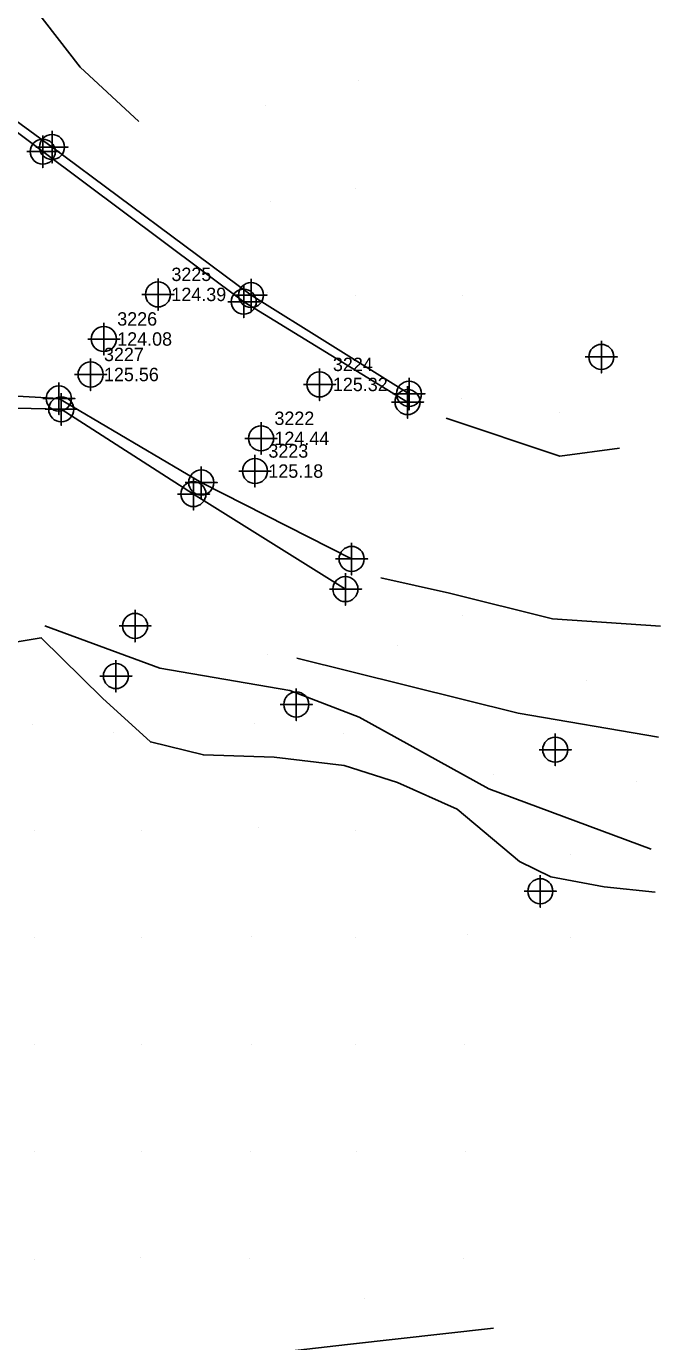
# Model space of a CAD drawing. Extents: x 2312183 to 2312663, y 819676 to 820746.
# Drawn here: x 2312544.8 to 2312663.2, y 819940.8 to 820186.5 of the extents above; entities that cross this region are included whole.
import ezdxf

# ---------------------------------------------------------------- set-up
doc = ezdxf.new("R2010")
doc.units = 0
for name, color, linetype in [('Exist DTM Breakline', 7, 'Continuous'), ('Exist DTM Breakline Cogo Point CELL', 7, 'Continuous'), ('Exist DTM Regular Point CELL', 7, 'Continuous'), ('Exist DTM Regular Point Underwater CELL', 7, 'Continuous'), ('Exist DTM Regular Point Underwater Cogo Elevation', 7, 'Continuous'), ('Exist DTM Regular Point Underwater Cogo Number', 7, 'Continuous'), ('Exist Hydro Stream or Body of Water', 7, 'Continuous'), ('Exist Hydro Stream or Body of Water Cogo Point CELL', 7, 'Continuous'), ('PH Exist DTM Breakline', 7, 'Continuous'), ('PH Exist DTM Point', 7, 'Continuous')]:
    doc.layers.add(name, color=color, linetype=linetype)

msp = doc.modelspace()

# ---------------------------------------------------------------- linework, layer by layer
at = {"layer": 'Exist DTM Breakline'}
for p, q in [((2312586.75, 820136.34), (2312616.24, 820117.89)), ((2312576, 820099.16), (2312604.37, 820081.4))]:
    msp.add_line(p, q, dxfattribs=at)
for points in [[(2312522.1, 820208.19), (2312528.71, 820183.41), (2312536.41, 820173.61), (2312549.61, 820163.99)], [(2312549.61, 820163.99), (2312586.75, 820136.34)], [(2312469.05, 820107.68), (2312503.56, 820116.05), (2312551.33, 820115), (2312576, 820099.16)]]:
    msp.add_lwpolyline(points, dxfattribs=at)
at = {"layer": 'Exist DTM Breakline Cogo Point CELL'}
for points in [[(2312549.61, 820166.99), (2312549.61, 820160.99), (2312549.61, 820163.99), (2312552.61, 820163.99), (2312546.61, 820163.99)], [(2312586.75, 820139.34), (2312586.75, 820133.34), (2312586.75, 820136.34), (2312589.75, 820136.34), (2312583.75, 820136.34)], [(2312616.24, 820120.89), (2312616.24, 820114.89), (2312616.24, 820117.89), (2312619.24, 820117.89), (2312613.24, 820117.89)], [(2312551.33, 820118), (2312551.33, 820112), (2312551.33, 820115), (2312554.33, 820115), (2312548.33, 820115)], [(2312576, 820102.16), (2312576, 820096.16), (2312576, 820099.16), (2312579, 820099.16), (2312573, 820099.16)], [(2312604.37, 820084.4), (2312604.37, 820078.4), (2312604.37, 820081.4), (2312607.37, 820081.4), (2312601.37, 820081.4)]]:
    msp.add_lwpolyline(points, dxfattribs=at)
for centre in [(2312549.61, 820163.99), (2312586.75, 820136.34), (2312616.24, 820117.89), (2312551.33, 820115), (2312576, 820099.16), (2312604.37, 820081.4)]:
    msp.add_circle(centre, 2.34, dxfattribs=at)
at = {"layer": 'Exist DTM Regular Point CELL'}
for points in [[(2312652.13, 820127.78), (2312652.13, 820121.78), (2312652.13, 820124.78), (2312655.13, 820124.78), (2312649.13, 820124.78)], [(2312565.11, 820077.53), (2312565.11, 820071.53), (2312565.11, 820074.53), (2312568.11, 820074.53), (2312562.11, 820074.53)], [(2312561.53, 820068.16), (2312561.53, 820062.16), (2312561.53, 820065.16), (2312564.53, 820065.16), (2312558.53, 820065.16)], [(2312595.2, 820062.85), (2312595.2, 820056.85), (2312595.2, 820059.85), (2312598.2, 820059.85), (2312592.2, 820059.85)], [(2312643.53, 820054.41), (2312643.53, 820048.41), (2312643.53, 820051.41), (2312646.53, 820051.41), (2312640.53, 820051.41)], [(2312640.74, 820027.96), (2312640.74, 820021.96), (2312640.74, 820024.96), (2312643.74, 820024.96), (2312637.74, 820024.96)]]:
    msp.add_lwpolyline(points, dxfattribs=at)
for centre in [(2312652.13, 820124.78), (2312565.11, 820074.53), (2312561.53, 820065.16), (2312595.2, 820059.85), (2312643.53, 820051.41), (2312640.74, 820024.96)]:
    msp.add_circle(centre, 2.34, dxfattribs=at)
at = {"layer": 'Exist DTM Regular Point Underwater CELL'}
for points in [[(2312569.39, 820139.46), (2312569.39, 820133.46), (2312569.39, 820136.46), (2312572.39, 820136.46), (2312566.39, 820136.46)], [(2312559.28, 820131.13), (2312559.28, 820125.13), (2312559.28, 820128.13), (2312562.28, 820128.13), (2312556.28, 820128.13)], [(2312556.81, 820124.5), (2312556.81, 820118.5), (2312556.81, 820121.5), (2312559.81, 820121.5), (2312553.81, 820121.5)], [(2312599.53, 820122.64), (2312599.53, 820116.64), (2312599.53, 820119.64), (2312602.53, 820119.64), (2312596.53, 820119.64)], [(2312588.62, 820112.57), (2312588.62, 820106.57), (2312588.62, 820109.57), (2312591.62, 820109.57), (2312585.62, 820109.57)], [(2312587.49, 820106.46), (2312587.49, 820100.46), (2312587.49, 820103.46), (2312590.49, 820103.46), (2312584.49, 820103.46)]]:
    msp.add_lwpolyline(points, dxfattribs=at)
for centre in [(2312569.39, 820136.46), (2312559.28, 820128.13), (2312556.81, 820121.5), (2312599.53, 820119.64), (2312588.62, 820109.57), (2312587.49, 820103.46)]:
    msp.add_circle(centre, 2.34, dxfattribs=at)
at = {"layer": 'Exist Hydro Stream or Body of Water'}
for p, q in [((2312585.39, 820135.1), (2312615.96, 820116.34)), ((2312577.46, 820101.32), (2312605.52, 820087.05))]:
    msp.add_line(p, q, dxfattribs=at)
for points in [[(2312524.84, 820178.65), (2312535.66, 820172.32), (2312547.88, 820163.13)], [(2312547.88, 820163.13), (2312585.39, 820135.1)], [(2312393.18, 820036.93), (2312414.57, 820059.59), (2312427.23, 820072.7), (2312438.05, 820092.67), (2312468.54, 820109.59), (2312503.07, 820119.67), (2312550.88, 820117.01)], [(2312550.88, 820117.01), (2312577.46, 820101.32)]]:
    msp.add_lwpolyline(points, dxfattribs=at)
at = {"layer": 'Exist Hydro Stream or Body of Water Cogo Point CELL'}
for points in [[(2312544.88, 820163.13), (2312550.88, 820163.13), (2312547.88, 820163.13), (2312547.88, 820160.13), (2312547.88, 820166.13)], [(2312582.39, 820135.1), (2312588.39, 820135.1), (2312585.39, 820135.1), (2312585.39, 820132.1), (2312585.39, 820138.1)], [(2312547.88, 820117.01), (2312553.88, 820117.01), (2312550.88, 820117.01), (2312550.88, 820114.01), (2312550.88, 820120.01)], [(2312612.96, 820116.34), (2312618.96, 820116.34), (2312615.96, 820116.34), (2312615.96, 820113.34), (2312615.96, 820119.34)], [(2312574.46, 820101.32), (2312580.46, 820101.32), (2312577.46, 820101.32), (2312577.46, 820098.32), (2312577.46, 820104.32)], [(2312602.52, 820087.05), (2312608.52, 820087.05), (2312605.52, 820087.05), (2312605.52, 820084.05), (2312605.52, 820090.05)]]:
    msp.add_lwpolyline(points, dxfattribs=at)
for centre in [(2312547.88, 820163.13), (2312585.39, 820135.1), (2312550.88, 820117.01), (2312615.96, 820116.34), (2312577.46, 820101.32), (2312605.52, 820087.05)]:
    msp.add_circle(centre, 2.34, dxfattribs=at)
at = {"layer": 'PH Exist DTM Breakline'}
for points in [[(2312531.48, 820219.81), (2312535.01, 820208.04), (2312541.96, 820195.62), (2312554.87, 820178.93), (2312565.84, 820168.78)], [(2312509.03, 820114.01), (2312517.15, 820110.06), (2312518.21, 820106.25), (2312517.15, 820100.47), (2312517.95, 820089.08), (2312520.08, 820081.64), (2312522.64, 820074.56), (2312526.51, 820071.39), (2312534, 820070.09), (2312547.61, 820072.32), (2312559.01, 820061.03), (2312567.96, 820052.87), (2312577.86, 820050.42), (2312591.06, 820050.01), (2312604.11, 820048.43), (2312614.06, 820045.26), (2312625.22, 820040.28), (2312636.84, 820030.53), (2312642.68, 820027.68), (2312652.67, 820025.8), (2312662.18, 820024.81)], [(2312623.16, 820113.36), (2312644.38, 820106.22), (2312655.5, 820107.75)], [(2312663.2, 820074.47), (2312643.01, 820075.86), (2312623.82, 820080.64), (2312610.97, 820083.52)], [(2312661.41, 820032.82), (2312631.11, 820044.08), (2312606.93, 820057.49), (2312594.01, 820062.47), (2312569.74, 820066.65), (2312548.24, 820074.57)], [(2312595.27, 820068.49), (2312636.63, 820058.21), (2312662.81, 820053.73)], [(2312513.82, 819939.75), (2312519.38, 819936.51), (2312526.86, 819933.99), (2312535.44, 819932.71), (2312543.63, 819933), (2312575.99, 819937.01), (2312604.73, 819940.27), (2312632.01, 819943.32)]]:
    msp.add_lwpolyline(points, dxfattribs=at)
at = {"layer": 'PH Exist DTM Point'}
for p, q in [((2312606.76, 820176.39), (2312606.76, 820176.39)), ((2312589.47, 820171.83), (2312589.47, 820171.83)), ((2312606.33, 820156.23), (2312606.33, 820156.23)), ((2312590.32, 820153.74), (2312590.32, 820153.74)), ((2312589.9, 820136.75), (2312589.9, 820136.75)), ((2312606.33, 820136.21), (2312606.33, 820136.21)), ((2312626.29, 820136.34), (2312626.29, 820136.34)), ((2312606.22, 820123.69), (2312606.22, 820123.69)), ((2312626.11, 820117.02), (2312626.11, 820117.02)), ((2312644.37, 820114.43), (2312644.37, 820114.43)), ((2312626.24, 820076.54), (2312626.24, 820076.54)), ((2312589.88, 820069.21), (2312589.88, 820069.21)), ((2312614.06, 820070.83), (2312614.06, 820070.83)), ((2312649.27, 820064.24), (2312649.27, 820064.24)), ((2312587.44, 820056.29), (2312587.44, 820056.29)), ((2312545.94, 820056.11), (2312545.94, 820056.11)), ((2312561.05, 820054.53), (2312561.05, 820054.53)), ((2312604, 820054.51), (2312604, 820054.51)), ((2312631.94, 820046.75), (2312631.94, 820046.75)), ((2312658.73, 820045.44), (2312658.73, 820045.44)), ((2312588.09, 820036.82), (2312588.09, 820036.82)), ((2312546.32, 820036.25), (2312546.32, 820036.25)), ((2312566.32, 820036.25), (2312566.32, 820036.25)), ((2312606.33, 820036.25), (2312606.33, 820036.25)), ((2312646.35, 820031.86), (2312646.35, 820031.86)), ((2312546.32, 820016.25), (2312546.32, 820016.25)), ((2312566.32, 820016.25), (2312566.32, 820016.25)), ((2312586.86, 820016.42), (2312586.86, 820016.42)), ((2312606.32, 820016.25), (2312606.32, 820016.25)), ((2312627.13, 820016.84), (2312627.13, 820016.84)), ((2312646.32, 820016.25), (2312646.32, 820016.25)), ((2312546.32, 819996.25), (2312546.32, 819996.25)), ((2312566.32, 819996.25), (2312566.32, 819996.25)), ((2312586.75, 819996.38), (2312586.75, 819996.38)), ((2312606.32, 819996.25), (2312606.32, 819996.25)), ((2312626.62, 819996.34), (2312626.62, 819996.34)), ((2312546.32, 819976.25), (2312546.32, 819976.25)), ((2312566.32, 819976.25), (2312566.32, 819976.25)), ((2312586.57, 819976.32), (2312586.57, 819976.32)), ((2312606.35, 819976.25), (2312606.35, 819976.25)), ((2312626.8, 819976.4), (2312626.8, 819976.4)), ((2312546.32, 819956.25), (2312546.32, 819956.25)), ((2312566.21, 819956.59), (2312566.21, 819956.59)), ((2312586.54, 819956.32), (2312586.54, 819956.32)), ((2312626.38, 819956.26), (2312626.38, 819956.26)), ((2312607.88, 819948.82), (2312607.88, 819948.82))]:
    msp.add_line(p, q, dxfattribs=at)

# ---------------------------------------------------------------- texts
at = {"layer": 'Exist DTM Regular Point Underwater Cogo Elevation'}
for s, p in [('124.39', (2312571.89, 820135.21)), ('124.08', (2312561.78, 820126.88)), ('125.56', (2312559.31, 820120.25)), ('125.32', (2312602.03, 820118.39)), ('124.44', (2312591.12, 820108.32)), ('125.18', (2312589.99, 820102.21))]:
    msp.add_text(s, height=2.5, dxfattribs=at).set_placement(p)
at = {"layer": 'Exist DTM Regular Point Underwater Cogo Number'}
for s, p in [('3225', (2312571.89, 820138.96)), ('3226', (2312561.78, 820130.63)), ('3227', (2312559.31, 820124)), ('3224', (2312602.03, 820122.14)), ('3222', (2312591.12, 820112.07)), ('3223', (2312589.99, 820105.96))]:
    msp.add_text(s, height=2.5, dxfattribs=at).set_placement(p)

doc.saveas('drawing.dxf')
